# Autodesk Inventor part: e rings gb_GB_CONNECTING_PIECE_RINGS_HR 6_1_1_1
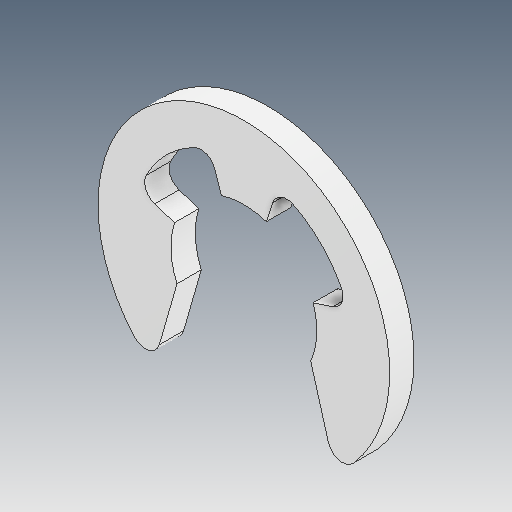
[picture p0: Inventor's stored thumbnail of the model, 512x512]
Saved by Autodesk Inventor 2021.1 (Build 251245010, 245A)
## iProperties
Created: 2021-05
Part Number: e rings gb_GB_CONNECTING_PIECE_RINGS_HR 6_1_1_1
Material: Ogólny
Document SubType Name: Modeling
Designer: user
Density: 1 g/cm^3
Appearance: Domyślna
Author: user
Revision Number: ÈÎºÎ
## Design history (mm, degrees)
feature "ÊäÈë1"
node "Bryła1"
